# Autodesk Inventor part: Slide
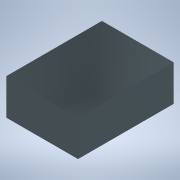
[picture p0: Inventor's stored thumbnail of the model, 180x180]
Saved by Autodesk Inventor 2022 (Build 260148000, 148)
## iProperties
Created: 2014-03
Part Number: Slide
Material: Lead
Document SubType Name: Modeling
Designer: John
Density: 1 g/cm^3
Appearance: Lead
Author: John
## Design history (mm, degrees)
sketch "Sketch1"
  geometry: L1 (0, 0)-(19.05, 0); L2 (19.05, 0)-(19.05, 9.525); L3 (19.05, 9.525)-(0, 9.525); L4 (0, 9.525)-(0, 0)
  constraints: 8 end point, 2 parallel, 1 horizontal, 1 perpendicular
  dimensions: "d0" = 19.05 distance of L2.end L3.end; "d1" = 9.525 distance of L3.end L1.start
extrude "Extrusion1" new body sketch "Sketch1" distance "d2" = 25.4; taper "d3" = 0 deg
body "Solid1"
